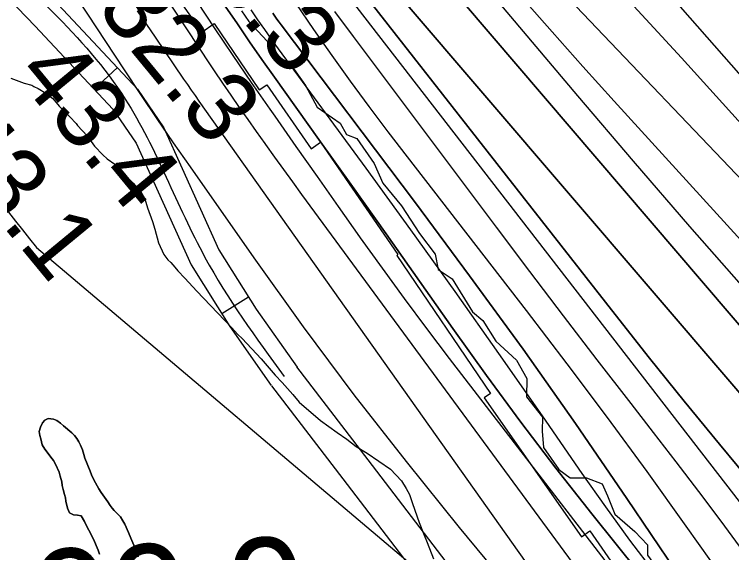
# Model space of a CAD drawing. Extents: x 3187622 to 3225504, y 800805 to 826213.
# Drawn here: x 3198678 to 3199360, y 816941 to 817453 of the extents above; entities that cross this region are included whole.
import ezdxf

# ---------------------------------------------------------------- set-up
doc = ezdxf.new("R2010")
doc.units = 0
for name, color, linetype in [('V-RIVR-EDGE', 7, 'Continuous'), ('V-RIVR-RANG', 7, 'Continuous'), ('V-ROAD-CNTR', 7, 'Continuous'), ('V-RRAP-RVMT', 7, 'Continuous'), ('V-SITE-VEGE', 7, 'Continuous'), ('V-SURV-IDEN', 7, 'Continuous'), ('V-TOPO-DPTH', 7, 'Continuous'), ('V-TOPO-MAJR', 7, 'Continuous'), ('V-TOPO-MINR', 7, 'Continuous'), ('V-TOPO-SHOR', 7, 'Continuous'), ('V-TOPO-WATR', 7, 'Continuous')]:
    doc.layers.add(name, color=color, linetype=linetype)

msp = doc.modelspace()

# ---------------------------------------------------------------- linework, layer by layer
at = {"layer": 'V-RIVR-EDGE'}
for points in [[(3198894.08, 817455.86), (3198901.01, 817445.85), (3198918.35, 817427.12), (3198927.88, 817413.18), (3198941.76, 817403.15), (3198954.76, 817384.86), (3198966.01, 817364.4), (3198987.71, 817349.14), (3198993.76, 817338.25), (3199003.75, 817334.32), (3199020.21, 817310.8), (3199028.42, 817292.09), (3199046.19, 817270.31), (3199063.08, 817244.19), (3199078.25, 817224.59), (3199080.82, 817209.81), (3199094.27, 817201.08), (3199113.75, 817169.74), (3199123.3, 817161.45), (3199135.85, 817141.86), (3199155.37, 817123.56), (3199165.32, 817106.15), (3199164.85, 817088.76), (3199180.01, 817069.6), (3199179.98, 817056.12), (3199181.24, 817040.47), (3199195.54, 817019.57), (3199206.38, 817011.72), (3199222.03, 817011.68), (3199236.8, 817005.99), (3199241.99, 816994.68)], [(3199241.99, 816994.68), (3199248.9, 816977.27), (3199267.98, 816960.71), (3199280.12, 816948.07), (3199280.1, 816938.08), (3199292.66, 816920.66), (3199314.77, 816896.7), (3199328.64, 816879.27), (3199332.52, 816868.4), (3199355.05, 816839.65), (3199365.88, 816823.11)]]:
    msp.add_lwpolyline(points, dxfattribs=at)
at = {"layer": 'V-ROAD-CNTR'}
for p, q in [((3198775.96, 817401.83), (3198754.07, 817381.31)), ((3198900.72, 817183.62), (3198875.32, 817167.66))]:
    msp.add_line(p, q, dxfattribs=at)
for points in [[(3198622.14, 817519.92), (3198697.88, 817441.28), (3198771.74, 817362.45), (3198793.87, 817329.97), (3198846.03, 817214.29), (3198882.83, 817155.7), (3198922.24, 817099.64)], [(3198719.63, 817461.94), (3198795.23, 817381.27), (3198820.14, 817344.69), (3198872.53, 817228.5), (3198907.82, 817172.31), (3198946.78, 817116.89)], [(3198946.43, 817117.37), (3199014.03, 817028.92), (3199117.2, 816894.19), (3199208.32, 816772.73), (3199250.15, 816715.2), (3199267.02, 816695.37), (3199303.52, 816657.94), (3199407.4, 816557.35), (3199448.89, 816521.06), (3199477.94, 816490.72), (3199519.63, 816443.58), (3199559.82, 816408.42), (3199578.38, 816394.16), (3199645.37, 816346.55), (3199666.18, 816326.75), (3199690.36, 816297.84), (3199711.55, 816262.64), (3199778.28, 816156.11), (3199849.33, 816073.21), (3199885.03, 816050.54), (3199905.28, 816049.42), (3199931.97, 816032.99)], [(3198922.6, 817099.16), (3198990.21, 817010.7), (3199093.29, 816876.06), (3199184.19, 816754.91), (3199226.56, 816696.64), (3199244.83, 816675.16), (3199282.34, 816636.69), (3199355.05, 816566.28)]]:
    msp.add_lwpolyline(points, dxfattribs=at)
msp.add_spline([(3197108.01, 817982.2), (3197162.34, 817991.13), (3197229.38, 818001.88), (3197259.08, 817993.64), (3197361.14, 818001.17), (3197493.79, 818058.56), (3197592.21, 818133.8), (3197727.97, 818194.32), (3197773.22, 818262.2), (3197795.85, 818360.06), (3197841.1, 818435.29), (3197893.71, 818488.46), (3197938.96, 818518.44), (3197968.94, 818533.71), (3198014.19, 818525.8), (3198044.74, 818495.82), (3198127.32, 818420.58), (3198203.12, 818307.45), (3198233.1, 818209.03), (3198255.73, 818133.8), (3198278.35, 818073.27), (3198323.61, 818005.39), (3198376.21, 817937.52), (3198429.38, 817900.18), (3198459.36, 817854.93), (3198466.72, 817832.3), (3198489.34, 817756.51), (3198504.61, 817703.9), (3198542.51, 817628.67), (3198633.02, 817530.24), (3198783.48, 817371.86), (3198859.28, 817221.4), (3198934.51, 817108.26)], degree=3, dxfattribs=at)
at = {"layer": 'V-RRAP-RVMT'}
for p, q in [((3198833.25, 817468.42), (3198856.19, 817435.63)), ((3198856.19, 817435.63), (3198867.89, 817443.72)), ((3198867.89, 817443.72), (3198910.77, 817380.68)), ((3198910.77, 817380.68), (3198918.01, 817385.63)), ((3198918.01, 817385.63), (3198960.35, 817324.75)), ((3198960.35, 817324.75), (3198969.07, 817330.83)), ((3198969.07, 817330.83), (3199042.78, 817224)), ((3199042.78, 817224), (3199041.64, 817223.24)), ((3199041.64, 817223.24), (3199130.7, 817092.01)), ((3199130.7, 817092.01), (3199124.6, 817087.72)), ((3199124.6, 817087.72), (3199217.27, 816955.73)), ((3199217.27, 816955.73), (3199225.08, 816961.21)), ((3199225.08, 816961.21), (3199291.59, 816865.62))]:
    msp.add_line(p, q, dxfattribs=at)
at = {"layer": 'V-SITE-VEGE'}
for p, q in [((3198674.66, 817391.7), (3198687.44, 817387.16)), ((3198687.44, 817387.16), (3198694.75, 817385.18)), ((3198694.75, 817385.18), (3198696.57, 817383.92)), ((3198696.57, 817383.92), (3198700.82, 817382)), ((3198700.82, 817382), (3198708.09, 817377.57)), ((3198708.09, 817377.57), (3198714.73, 817372.54)), ((3198714.73, 817372.54), (3198720.71, 817365.07)), ((3198720.71, 817365.07), (3198725.52, 817360.08)), ((3198725.52, 817360.08), (3198730.94, 817355.07)), ((3198730.94, 817355.07), (3198736.94, 817348.83)), ((3198736.94, 817348.83), (3198738.13, 817346.96)), ((3198738.13, 817346.96), (3198747.13, 817336.99)), ((3198747.13, 817336.99), (3198754.29, 817327.04)), ((3198754.29, 817327.04), (3198762.1, 817318.93)), ((3198762.1, 817318.93), (3198766.32, 817315.17)), ((3198766.32, 817315.17), (3198773.58, 817310.13)), ((3198773.58, 817310.13), (3198791, 817292.02)), ((3198791, 817292.02), (3198796.99, 817285.16)), ((3198796.99, 817285.16), (3198799.38, 817282.05)), ((3198799.38, 817282.05), (3198801.75, 817277.72)), ((3198801.75, 817277.72), (3198802.9, 817274.02)), ((3198802.9, 817274.02), (3198804.64, 817268.47)), ((3198804.64, 817268.47), (3198809.29, 817255.51)), ((3198809.29, 817255.51), (3198811.59, 817248.12)), ((3198811.59, 817248.12), (3198815.02, 817235.18)), ((3198815.02, 817235.18), (3198820.32, 817224.05)), ((3198820.32, 817224.05), (3198823.9, 817219.08)), ((3198823.9, 817219.08), (3198826.92, 817216.57)), ((3198826.92, 817216.57), (3198830.51, 817212.21)), ((3198830.51, 817212.21), (3198833.5, 817208.47)), ((3198833.5, 817208.47), (3198840.11, 817201.61)), ((3198840.11, 817201.61), (3198851.51, 817189.13)), ((3198851.51, 817189.13), (3198884.55, 817154.79)), ((3198884.55, 817154.79), (3198890.54, 817147.93)), ((3198890.54, 817147.93), (3198894.76, 817144.18)), ((3198894.76, 817144.18), (3198912.77, 817124.83)), ((3198912.77, 817124.83), (3198925.95, 817109.26)), ((3198925.95, 817109.26), (3198932.56, 817102.39)), ((3198932.56, 817102.39), (3198942.76, 817091.16)), ((3198942.76, 817091.16), (3198948.74, 817083.69)), ((3198948.74, 817083.69), (3198969.24, 817066.14)), ((3198704.66, 817063.97), (3198702.79, 817059.78)), ((3198707.15, 817066.68), (3198704.66, 817063.97)), ((3198710.27, 817068.08), (3198707.15, 817066.68)), ((3198715.14, 817067.67), (3198710.27, 817068.08)), ((3198718.35, 817066.14), (3198715.14, 817067.67)), ((3198721.88, 817063.63), (3198718.35, 817066.14)), ((3198969.24, 817066.14), (3198984.95, 817054.81)), ((3198702.79, 817059.78), (3198701.74, 817055.73)), ((3198724.92, 817061.14), (3198721.88, 817063.63)), ((3198732.76, 817054.65), (3198724.92, 817061.14)), ((3198701.74, 817055.73), (3198702.16, 817052.15)), ((3198702.16, 817052.15), (3198703.23, 817048.88)), ((3198735.15, 817052), (3198732.76, 817054.65)), ((3198737.37, 817049.19), (3198735.15, 817052)), ((3198984.95, 817054.81), (3198994.02, 817048.51)), ((3198703.23, 817048.88), (3198704.59, 817043.16)), ((3198739.26, 817046.07), (3198737.37, 817049.19)), ((3198740.82, 817042.95), (3198739.26, 817046.07)), ((3198994.02, 817048.51), (3199003.08, 817041.59)), ((3198704.59, 817043.16), (3198706.94, 817038.89)), ((3198706.94, 817038.89), (3198710.27, 817034.77)), ((3198742.85, 817038.53), (3198740.82, 817042.95)), ((3198744.06, 817033.79), (3198742.85, 817038.53)), ((3199003.08, 817041.59), (3199013.38, 817035.26)), ((3198710.27, 817034.77), (3198712.81, 817031.47)), ((3198712.81, 817031.47), (3198715.19, 817028.33)), ((3198745.13, 817030.36), (3198744.06, 817033.79)), ((3198750.09, 817018.23), (3198745.13, 817030.36)), ((3199013.38, 817035.26), (3199035.75, 817020.12)), ((3198715.19, 817028.33), (3198717.07, 817024.72)), ((3198717.07, 817024.72), (3198720.66, 817017.18)), ((3198720.66, 817017.18), (3198721.56, 817013.42)), ((3198751.49, 817014.47), (3198750.09, 817018.23)), ((3199035.75, 817020.12), (3199045.96, 817008.9)), ((3198721.56, 817013.42), (3198723.08, 817007.86)), ((3198753.36, 817010.53), (3198751.49, 817014.47)), ((3198755.08, 817006.92), (3198753.36, 817010.53)), ((3198723.08, 817007.86), (3198723.67, 817004.44)), ((3198723.67, 817004.44), (3198724.4, 817000.69)), ((3198758.22, 817001.34), (3198755.08, 817006.92)), ((3199045.96, 817008.9), (3199050.71, 817001.45)), ((3198724.4, 817000.69), (3198725.77, 816995.95)), ((3198725.77, 816995.95), (3198726.53, 816992.85)), ((3198760.59, 816997.88), (3198758.22, 817001.34)), ((3198767.08, 816988.82), (3198760.59, 816997.88)), ((3199050.71, 817001.45), (3199053.67, 816995.88)), ((3199053.67, 816995.88), (3199056.56, 816987.25)), ((3198726.53, 816992.85), (3198726.95, 816989.59)), ((3198726.95, 816989.59), (3198728.45, 816983.06)), ((3198728.45, 816983.06), (3198730.48, 816978.47)), ((3198769.13, 816985.53), (3198767.08, 816988.82)), ((3198771.03, 816983.05), (3198769.13, 816985.53)), ((3198773.1, 816980.57), (3198771.03, 816983.05)), ((3199056.56, 816987.25), (3199062.96, 816969.35)), ((3198730.48, 816978.47), (3198734.34, 816976.61)), ((3198734.34, 816976.61), (3198738.08, 816976.38)), ((3198738.08, 816976.38), (3198741.63, 816975.49)), ((3198741.63, 816975.49), (3198744.62, 816970.23)), ((3198778.83, 816974.61), (3198773.1, 816980.57)), ((3198744.62, 816970.23), (3198747.12, 816965.31)), ((3198781.2, 816970.99), (3198778.83, 816974.61)), ((3198783.08, 816967.54), (3198781.2, 816970.99)), ((3199062.96, 816969.35), (3199067.05, 816958.85)), ((3198747.12, 816965.31), (3198749.01, 816961.86)), ((3198749.01, 816961.86), (3198753.4, 816953.49)), ((3198786.67, 816959.83), (3198783.08, 816967.54)), ((3198788.68, 816954.43), (3198786.67, 816959.83)), ((3199067.05, 816958.85), (3199070.56, 816950.21)), ((3198753.4, 816953.49), (3198757.58, 816942.84)), ((3198791.64, 816947.71), (3198788.68, 816954.43)), ((3199070.56, 816950.21), (3199076.39, 816934.78)), ((3198757.58, 816942.84), (3198759.13, 816939.08)), ((3198793.5, 816942.96), (3198791.64, 816947.71)), ((3198795.81, 816936.58), (3198793.5, 816942.96))]:
    msp.add_line(p, q, dxfattribs=at)
at = {"layer": 'V-TOPO-DPTH'}
for points in [[(3199434.71, 817078.35), (3199079.61, 817493.74)], [(3199079.61, 817493.74), (3199434.71, 817078.35)], [(3199381.94, 817003.29), (3199348.31, 817043.81), (3199314.95, 817084.56), (3199282, 817125.64), (3199249.34, 817166.94), (3199005.9, 817477.94)], [(3199005.9, 817477.94), (3199249.34, 817166.94), (3199282, 817125.64), (3199314.95, 817084.56), (3199348.31, 817043.81), (3199381.94, 817003.29)], [(3199441.69, 817006), (3199045.79, 817468.69)], [(3199045.79, 817468.69), (3199441.69, 817006)], [(3199367.42, 816806.6), (3199359.68, 816814.56), (3199352.13, 816822.69), (3199344.85, 816831.06), (3199337.76, 816839.6), (3199226.91, 816977.64), (3199192.87, 817020.9), (3199159.41, 817064.59), (3199126.82, 817108.93), (3199094.81, 817153.71), (3199063.17, 817198.77), (3199031.44, 817243.76), (3198999.58, 817288.67), (3198967.64, 817333.51), (3198925.28, 817392.8), (3198913.41, 817409.57), (3198901.66, 817426.42), (3198890.07, 817443.38), (3198878.59, 817460.42)], [(3199361.93, 816843), (3199359.62, 816845.97), (3199357.37, 816848.98), (3199355.18, 816852.04), (3199353.03, 816855.14), (3199260.38, 816992.08), (3199211.4, 817063.28), (3199161.7, 817133.97), (3199110.92, 817203.88), (3199059.42, 817273.27), (3198931.86, 817442.41), (3198929.77, 817445.21), (3198927.7, 817448.03), (3198925.67, 817450.87), (3198923.65, 817453.73)], [(3198923.65, 817453.73), (3198925.67, 817450.87), (3198927.7, 817448.03), (3198929.77, 817445.21), (3198931.86, 817442.41), (3199059.42, 817273.27), (3199110.92, 817203.88), (3199161.7, 817133.97), (3199211.4, 817063.28), (3199260.38, 816992.08), (3199353.03, 816855.14), (3199355.18, 816852.04), (3199357.37, 816848.98), (3199359.62, 816845.97), (3199361.93, 816843)], [(3198982.55, 817455.21), (3199000.01, 817431.46), (3199136.08, 817250.04), (3199167.82, 817207.93), (3199199.71, 817165.93), (3199231.81, 817124.1), (3199264.06, 817082.37), (3199285.37, 817054.93), (3199306.95, 817026.92), (3199328.38, 816998.8), (3199349.59, 816970.51), (3199370.64, 816942.11)], [(3198982.55, 817455.21), (3199000.01, 817431.46), (3199136.08, 817250.04), (3199167.82, 817207.93), (3199199.71, 817165.93), (3199231.81, 817124.1), (3199264.06, 817082.37), (3199285.37, 817054.93), (3199306.95, 817026.92), (3199328.38, 816998.8), (3199349.59, 816970.51), (3199370.64, 816942.11)]]:
    msp.add_lwpolyline(points, dxfattribs=at)
at = {"layer": 'V-TOPO-MAJR'}
for points in [[(3198342.95, 818716.99), (3198374.42, 818659.39), (3198405.82, 818601.75), (3198437.12, 818544.05), (3198468.34, 818486.32), (3198675.34, 818102.78), (3198687.67, 818080.41), (3198700.27, 818058.2), (3198713.26, 818036.21), (3198726.51, 818014.37), (3198740.23, 817992.83), (3198754.3, 817971.53), (3198768.89, 817950.58), (3198783.84, 817929.87), (3199038.64, 817585.91), (3199049.32, 817571.77), (3199060.18, 817557.77), (3199071.3, 817543.98), (3199082.59, 817530.32), (3199213.51, 817375.02), (3199266.5, 817312.77), (3199319.89, 817250.88), (3199373.89, 817189.52)], [(3198794.77, 817455.84), (3198811.85, 817430.69), (3198838.98, 817391.04), (3198842.6, 817385.78), (3198846.23, 817380.54), (3198849.89, 817375.31), (3198853.57, 817370.09), (3199200.23, 816880.77), (3199214.83, 816860.63), (3199229.73, 816840.71), (3199245.06, 816821.12), (3199260.67, 816801.76), (3199288.64, 816767.86), (3199290.53, 816765.65), (3199292.48, 816763.49), (3199294.51, 816761.41), (3199296.59, 816759.37), (3199403.41, 816658.82)]]:
    msp.add_lwpolyline(points, dxfattribs=at)
at = {"layer": 'V-TOPO-MINR'}
for points in [[(3198349.13, 818785.06), (3198502.32, 818505.68), (3198541.3, 818435.29), (3198580.69, 818365.14), (3198620.67, 818295.32), (3198661.05, 818225.73), (3198725.88, 818115.13), (3198734.3, 818101.11), (3198742.92, 818087.21), (3198751.85, 818073.51), (3198760.97, 818059.94), (3199041.41, 817652.3), (3199049.56, 817640.74), (3199057.88, 817629.32), (3199066.46, 817618.09), (3199075.22, 817606.98), (3199084.24, 817596.09), (3199093.43, 817585.36), (3199102.89, 817574.85), (3199112.52, 817564.5), (3199476.76, 817182.58)], [(3198419.45, 818715.85), (3198626.69, 818321.97), (3198647.16, 818283.7), (3198667.98, 818245.63), (3198689.32, 818207.85), (3198711.01, 818170.26), (3198746.01, 818110.58), (3198750.55, 818103.04), (3198755.22, 818095.57), (3198760.06, 818088.22), (3198765.02, 818080.95), (3198830.36, 817987.6), (3198868.72, 817934.2), (3198907.92, 817881.44), (3198948.4, 817829.65), (3198989.73, 817778.51), (3199096.02, 817650.22), (3199111.57, 817631.74), (3199127.31, 817613.43), (3199143.34, 817595.36), (3199159.55, 817577.46), (3199252.09, 817476.87), (3199312.31, 817411.03), (3199372.27, 817344.96)], [(3198214.61, 818677.59), (3198226.59, 818658.48), (3198600.84, 818064.65), (3198618.08, 818037.34), (3198635.34, 818010.04), (3198652.64, 817982.76), (3198669.96, 817955.5), (3198703.5, 817902.8), (3198737.84, 817849.36), (3198772.52, 817796.13), (3198807.68, 817743.23), (3198843.16, 817690.53), (3198956.53, 817523.83), (3198967.97, 817507.34), (3198979.61, 817491), (3198991.55, 817474.87), (3199003.69, 817458.89), (3199374.89, 816979.49)], [(3198679.72, 817684.37), (3198852.66, 817421.96), (3198860.39, 817410.31), (3198868.17, 817398.7), (3198876.02, 817387.13), (3198883.92, 817375.59), (3198891.89, 817364.1), (3198899.89, 817352.64), (3198907.94, 817341.21), (3198916.03, 817329.81), (3198916.8, 817328.73), (3198925.33, 817316.82), (3198933.89, 817304.94), (3198942.51, 817293.1), (3198951.15, 817281.28), (3199277.02, 816837.78), (3199296.44, 816812.18), (3199316.37, 816787), (3199337.07, 816762.44), (3199358.27, 816738.3), (3199380.13, 816714.74)], [(3198614.63, 817654.73), (3198782.4, 817399.66), (3198797.83, 817376.43), (3198813.4, 817353.29), (3198829.17, 817330.28), (3198845.07, 817307.36), (3198905.63, 817220.91), (3198952.69, 817155.42), (3199000.77, 817090.72), (3199050.4, 817027.19), (3199101.06, 816964.44), (3199262.66, 816769.12), (3199270.79, 816759.56), (3199279.08, 816750.15), (3199287.61, 816740.96), (3199296.31, 816731.92), (3199525.78, 816499.7)], [(3199255.47, 817522.96), (3199583.71, 817149.69)], [(3199079.61, 817493.74), (3199434.71, 817078.35)], [(3198512.51, 817477.93), (3198555.48, 817420.28), (3198672.57, 817264.51), (3198679.08, 817255.98), (3198685.66, 817247.49), (3198692.35, 817239.1), (3198699.12, 817230.76), (3199082.72, 816906.29), (3199208.96, 816753.47), (3199225.58, 816733.51), (3199242.29, 816713.62), (3199259.15, 816693.86), (3199276.11, 816674.18), (3199293.26, 816654.66), (3199310.55, 816635.28), (3199328.07, 816616.11), (3199345.74, 816597.06)], [(3199005.9, 817477.94), (3199249.34, 817166.94), (3199282, 817125.64), (3199314.95, 817084.56), (3199348.31, 817043.81), (3199381.94, 817003.29)], [(3199045.79, 817468.69), (3199441.69, 817006)], [(3199160.38, 817469.02), (3199189.33, 817435.75), (3199218.62, 817402.79), (3199248.15, 817370.04), (3199511.91, 817080.44)], [(3198851.41, 817464.63), (3198868.53, 817438.89), (3198885.78, 817413.25), (3198903.25, 817387.76), (3198920.87, 817362.36), (3198925.58, 817355.63), (3198945.67, 817326.95), (3198965.8, 817298.3), (3198985.97, 817269.67), (3199006.18, 817241.07), (3199006.91, 817240.03), (3199027.68, 817211.05), (3199048.67, 817182.23), (3199070.01, 817153.68), (3199091.58, 817125.29), (3199309.66, 816841.79), (3199323.28, 816824.66), (3199337.25, 816807.84), (3199351.76, 816791.47), (3199366.63, 816775.42)], [(3198878.59, 817460.42), (3198890.07, 817443.38), (3198901.66, 817426.42), (3198913.41, 817409.57), (3198925.28, 817392.8), (3198967.64, 817333.51), (3198999.58, 817288.67), (3199031.44, 817243.76), (3199063.17, 817198.77), (3199094.81, 817153.71), (3199126.82, 817108.93), (3199159.41, 817064.59), (3199192.87, 817020.9), (3199226.91, 816977.64), (3199337.76, 816839.6), (3199344.85, 816831.06), (3199352.13, 816822.69), (3199359.68, 816814.56), (3199367.42, 816806.6)], [(3198945.7, 817462.82), (3198962.58, 817438), (3198979.78, 817413.4), (3198997.37, 817389.07), (3199015.15, 817364.87), (3199033.2, 817340.89), (3199051.45, 817317.04), (3199164.72, 817170.75), (3199203.43, 817120.09), (3199241.71, 817069.11), (3199279.33, 817017.64), (3199316.51, 816965.85), (3199351.46, 816916.49), (3199371.27, 816889.48)], [(3198902.94, 817456.73), (3198909.33, 817447.42), (3198915.79, 817438.15), (3198922.35, 817428.95), (3198928.98, 817419.8), (3199012.18, 817306.2), (3199054.64, 817247.71), (3199096.76, 817189), (3199138.39, 817129.93), (3199179.69, 817070.63), (3199217.48, 817015.9), (3199239.97, 816984.04), (3199262.9, 816952.5), (3199286.49, 816921.45), (3199310.51, 816890.72), (3199351.98, 816838.82), (3199355.69, 816834.37), (3199359.51, 816830.04), (3199363.52, 816825.87)], [(3198982.55, 817455.21), (3199000.01, 817431.46), (3199136.08, 817250.04), (3199167.82, 817207.93), (3199199.71, 817165.93), (3199231.81, 817124.1), (3199264.06, 817082.37), (3199285.37, 817054.93), (3199306.95, 817026.92), (3199328.38, 816998.8), (3199349.59, 816970.51), (3199370.64, 816942.11)]]:
    msp.add_lwpolyline(points, dxfattribs=at)
at = {"layer": 'V-TOPO-SHOR'}
for points in [[(3198759.13, 816939.08), (3198757.58, 816942.84), (3198753.4, 816953.49), (3198749.01, 816961.86), (3198747.12, 816965.31), (3198744.62, 816970.23), (3198741.63, 816975.49), (3198738.08, 816976.37), (3198734.34, 816976.61), (3198730.48, 816978.47), (3198728.45, 816983.06), (3198726.95, 816989.59), (3198726.53, 816992.85), (3198725.77, 816995.95), (3198724.4, 817000.69), (3198723.67, 817004.44), (3198723.08, 817007.86), (3198721.56, 817013.42), (3198720.66, 817017.18), (3198717.07, 817024.72), (3198715.19, 817028.33), (3198712.81, 817031.47), (3198710.27, 817034.77), (3198706.94, 817038.89), (3198704.59, 817043.16), (3198703.23, 817048.88), (3198702.16, 817052.15), (3198701.74, 817055.73), (3198702.79, 817059.78), (3198704.66, 817063.97), (3198707.15, 817066.68), (3198710.27, 817068.08), (3198715.14, 817067.67), (3198718.35, 817066.14), (3198721.88, 817063.63), (3198724.92, 817061.14), (3198732.76, 817054.65), (3198735.15, 817052), (3198737.37, 817049.2), (3198739.26, 817046.07), (3198740.82, 817042.95), (3198742.85, 817038.53), (3198744.06, 817033.79), (3198745.13, 817030.36), (3198750.1, 817018.23), (3198751.49, 817014.47), (3198753.36, 817010.53), (3198755.08, 817006.92)], [(3198755.08, 817006.92), (3198758.22, 817001.34), (3198760.59, 816997.88), (3198767.08, 816988.82), (3198769.13, 816985.53), (3198771.03, 816983.05), (3198773.1, 816980.57), (3198778.83, 816974.61), (3198781.2, 816970.99), (3198783.08, 816967.54), (3198786.67, 816959.83), (3198788.68, 816954.43), (3198791.64, 816947.71), (3198793.5, 816942.96), (3198795.81, 816936.58)]]:
    msp.add_lwpolyline(points, dxfattribs=at)
at = {"layer": 'V-TOPO-WATR'}
msp.add_lwpolyline([(3198923.65, 817453.73), (3198925.67, 817450.87), (3198927.7, 817448.03), (3198929.77, 817445.21), (3198931.86, 817442.41), (3199059.42, 817273.27), (3199110.92, 817203.88), (3199161.7, 817133.97), (3199211.4, 817063.28), (3199260.38, 816992.08), (3199353.03, 816855.14), (3199355.18, 816852.04), (3199357.37, 816848.98), (3199359.62, 816845.97), (3199361.93, 816843)], dxfattribs=at)

# ---------------------------------------------------------------- texts
at = {"layer": 'V-RIVR-RANG'}
for s, rotation, p in [('6.3', 309.76153, (3198861.22, 817486.38)), ('32.3', 309.49833, (3198754.67, 817458.94)), ('43.4', 309.49833, (3198677.67, 817395.14)), ('43.1', 309.49833, (3198602.17, 817329.51))]:
    msp.add_text(s, height=67, rotation=rotation, dxfattribs=at).set_placement(p)
at = {"layer": 'V-SURV-IDEN'}
msp.add_text('1422+99.9', height=100, rotation=3.20814, dxfattribs=at).set_placement((3198323.67, 816821.41))

doc.saveas('drawing.dxf')
